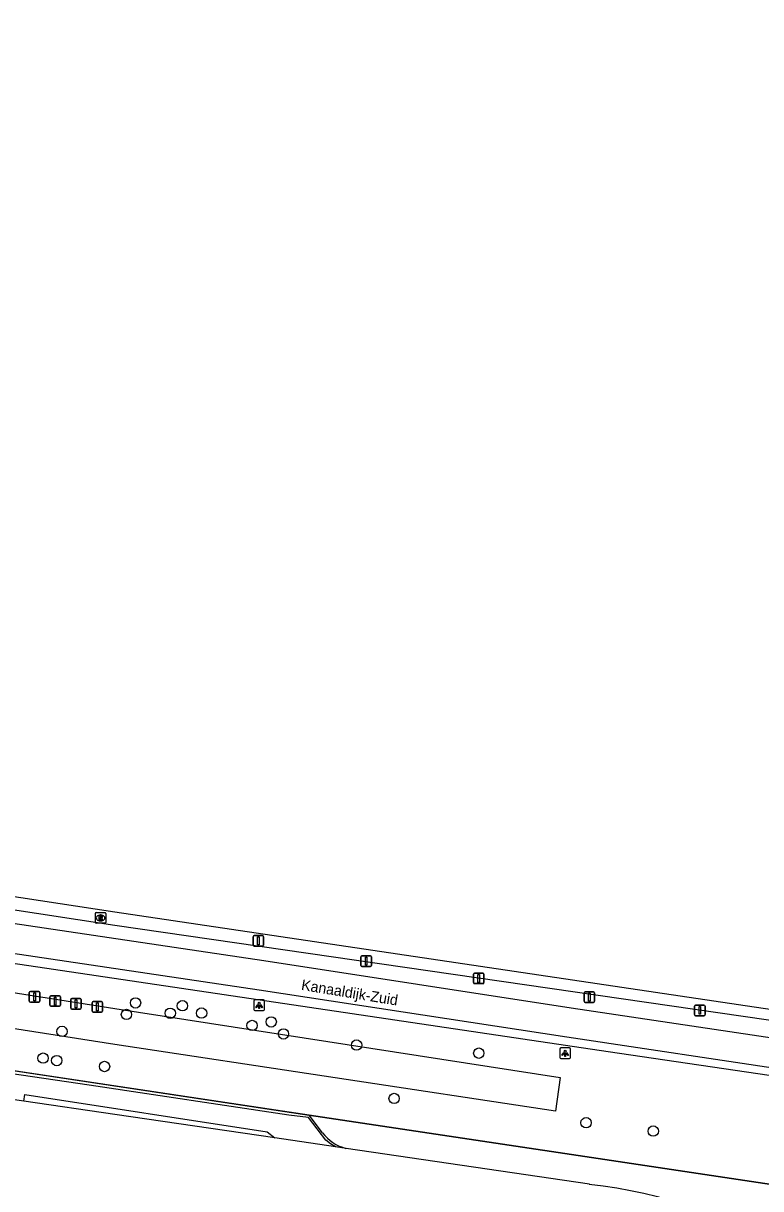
# Model space of a CAD drawing. Extents: x 163046 to 165074, y 382019 to 382874.
# Drawn here: x 164491.3 to 164561, y 382621 to 382731.1 of the extents above; entities that cross this region are included whole.
import ezdxf

# ---------------------------------------------------------------- set-up
doc = ezdxf.new("R2010")
doc.units = 0
for name, color, linetype in [('IMGEO_Afsluitpaal', 7, 'Continuous'), ('IMGEO_Boom', 7, 'Continuous'), ('IMGEO_Fietspad_gesloten', 7, 'Continuous'), ('IMGEO_Groenvoorziening', 7, 'Continuous'), ('IMGEO_Hek', 7, 'Continuous'), ('IMGEO_Lichtpunt', 7, 'Continuous'), ('IMGEO_Openbare_ruimte_label', 7, 'Continuous'), ('IMGEO_Rijbaan_lokaal_gesloten', 7, 'Continuous'), ('IMGEO_Rijbaan_lokaal_halfverhard', 7, 'Continuous'), ('IMGEO_Rioolput', 7, 'Continuous'), ('IMGEO_Waterloop', 7, 'Continuous')]:
    doc.layers.add(name, color=color, linetype=linetype)

msp = doc.modelspace()

# ---------------------------------------------------------------- linework, layer by layer
at = {"layer": 'IMGEO_Afsluitpaal'}
for p, q in [((164513.06, 382643.99), (164513.06, 382644.79)), ((164513.06, 382644.79), (164513.06, 382643.99)), ((164513.16, 382644.89), (164513.95, 382644.89)), ((164513.95, 382644.89), (164513.16, 382644.89)), ((164514.05, 382644.79), (164514.05, 382643.99)), ((164514.05, 382643.99), (164514.05, 382644.79)), ((164513.95, 382643.89), (164513.16, 382643.89)), ((164513.16, 382643.89), (164513.95, 382643.89)), ((164523.25, 382642.07), (164523.25, 382642.87)), ((164523.25, 382642.87), (164523.25, 382642.07)), ((164523.35, 382642.97), (164524.14, 382642.97)), ((164524.14, 382642.97), (164523.35, 382642.97)), ((164524.14, 382641.97), (164523.35, 382641.97)), ((164523.35, 382641.97), (164524.14, 382641.97)), ((164524.24, 382642.87), (164524.24, 382642.07)), ((164524.24, 382642.07), (164524.24, 382642.87)), ((164533.89, 382640.45), (164533.89, 382641.25)), ((164533.89, 382641.25), (164533.89, 382640.45)), ((164533.99, 382641.35), (164534.78, 382641.35)), ((164534.78, 382641.35), (164533.99, 382641.35)), ((164534.88, 382641.25), (164534.88, 382640.45)), ((164534.88, 382640.45), (164534.88, 382641.25)), ((164534.78, 382640.35), (164533.99, 382640.35)), ((164533.99, 382640.35), (164534.78, 382640.35)), ((164491.91, 382638.71), (164491.91, 382639.51)), ((164491.91, 382639.51), (164491.91, 382638.71)), ((164492.01, 382639.61), (164492.8, 382639.61)), ((164492.8, 382639.61), (164492.01, 382639.61)), ((164492.8, 382638.61), (164492.01, 382638.61)), ((164492.01, 382638.61), (164492.8, 382638.61)), ((164492.9, 382639.51), (164492.9, 382638.71)), ((164492.9, 382638.71), (164492.9, 382639.51)), ((164493.86, 382638.31), (164493.86, 382639.11)), ((164493.86, 382639.11), (164493.86, 382638.31)), ((164493.96, 382639.21), (164494.75, 382639.21)), ((164494.75, 382639.21), (164493.96, 382639.21)), ((164494.85, 382639.11), (164494.85, 382638.31)), ((164494.85, 382638.31), (164494.85, 382639.11)), ((164495.82, 382638.05), (164495.82, 382638.85)), ((164495.82, 382638.85), (164495.82, 382638.05)), ((164495.92, 382638.95), (164496.71, 382638.95)), ((164496.71, 382638.95), (164495.92, 382638.95)), ((164496.81, 382638.85), (164496.81, 382638.05)), ((164496.81, 382638.05), (164496.81, 382638.85)), ((164497.95, 382638.65), (164498.74, 382638.65)), ((164498.74, 382638.65), (164497.95, 382638.65)), ((164544.34, 382638.68), (164544.34, 382639.48)), ((164544.34, 382639.48), (164544.34, 382638.68)), ((164544.44, 382639.58), (164545.22, 382639.58)), ((164545.22, 382639.58), (164544.44, 382639.58)), ((164545.32, 382639.48), (164545.32, 382638.68)), ((164545.32, 382638.68), (164545.32, 382639.48)), ((164494.75, 382638.21), (164493.96, 382638.21)), ((164493.96, 382638.21), (164494.75, 382638.21)), ((164496.71, 382637.95), (164495.92, 382637.95)), ((164495.92, 382637.95), (164496.71, 382637.95)), ((164497.85, 382637.75), (164497.85, 382638.55)), ((164497.85, 382638.55), (164497.85, 382637.75)), ((164498.74, 382637.65), (164497.95, 382637.65)), ((164497.95, 382637.65), (164498.74, 382637.65)), ((164498.84, 382638.55), (164498.84, 382637.75)), ((164498.84, 382637.75), (164498.84, 382638.55)), ((164545.22, 382638.58), (164544.44, 382638.58)), ((164544.44, 382638.58), (164545.22, 382638.58)), ((164554.78, 382637.42), (164554.78, 382638.22)), ((164554.78, 382638.22), (164554.78, 382637.42)), ((164554.88, 382638.32), (164555.67, 382638.32)), ((164555.67, 382638.32), (164554.88, 382638.32)), ((164555.77, 382638.22), (164555.77, 382637.42)), ((164555.77, 382637.42), (164555.77, 382638.22)), ((164555.67, 382637.32), (164554.88, 382637.32)), ((164554.88, 382637.32), (164555.67, 382637.32))]:
    msp.add_line(p, q, dxfattribs=at)
for points in [[(164513.48, 382644.77), (164513.63, 382644.77), (164513.63, 382644.02), (164513.48, 382644.02), (164513.48, 382644.77)], [(164523.67, 382642.85), (164523.82, 382642.85), (164523.82, 382642.1), (164523.67, 382642.1), (164523.67, 382642.85)], [(164534.31, 382641.22), (164534.46, 382641.22), (164534.46, 382640.47), (164534.31, 382640.47), (164534.31, 382641.22)], [(164492.33, 382639.49), (164492.48, 382639.49), (164492.48, 382638.74), (164492.33, 382638.74), (164492.33, 382639.49)], [(164494.28, 382639.08), (164494.43, 382639.08), (164494.43, 382638.33), (164494.28, 382638.33), (164494.28, 382639.08)], [(164496.24, 382638.82), (164496.39, 382638.82), (164496.39, 382638.07), (164496.24, 382638.07), (164496.24, 382638.82)], [(164544.75, 382639.45), (164544.9, 382639.45), (164544.9, 382638.7), (164544.75, 382638.7), (164544.75, 382639.45)], [(164498.27, 382638.53), (164498.42, 382638.53), (164498.42, 382637.78), (164498.27, 382637.78), (164498.27, 382638.53)], [(164555.2, 382638.2), (164555.35, 382638.2), (164555.35, 382637.45), (164555.2, 382637.45), (164555.2, 382638.2)]]:
    msp.add_lwpolyline(points, dxfattribs=at)
for centre, start, end in [((164513.16, 382644.79), 90, 180), ((164513.16, 382644.79), 90, 180), ((164513.95, 382644.79), 0, 90), ((164513.95, 382644.79), 360, 90), ((164513.16, 382643.99), 180, 270), ((164513.16, 382643.99), 180, 270), ((164513.95, 382643.99), 270, 0), ((164513.95, 382643.99), 270, 0), ((164523.35, 382642.87), 90, 180), ((164523.35, 382642.87), 90, 180), ((164523.35, 382642.07), 180, 270), ((164523.35, 382642.07), 180, 270), ((164524.14, 382642.87), 0, 90), ((164524.14, 382642.87), 360, 90), ((164524.14, 382642.07), 270, 0), ((164524.14, 382642.07), 270, 0), ((164533.99, 382641.25), 90, 180), ((164533.99, 382641.25), 90, 180), ((164534.78, 382641.25), 0, 90), ((164534.78, 382641.25), 360, 90), ((164533.99, 382640.45), 180, 270), ((164533.99, 382640.45), 180, 270), ((164534.78, 382640.45), 270, 0), ((164534.78, 382640.45), 270, 0), ((164492.01, 382639.51), 90, 180), ((164492.01, 382639.51), 90, 180), ((164492.01, 382638.71), 180, 270), ((164492.01, 382638.71), 180, 270), ((164492.8, 382639.51), 0, 90), ((164492.8, 382639.51), 360, 90), ((164492.8, 382638.71), 270, 0), ((164492.8, 382638.71), 270, 0), ((164493.96, 382639.11), 90, 180), ((164493.96, 382639.11), 90, 180), ((164494.75, 382639.11), 0, 90), ((164494.75, 382639.11), 360, 90), ((164495.92, 382638.85), 90, 180), ((164495.92, 382638.85), 90, 180), ((164496.71, 382638.85), 0, 90), ((164496.71, 382638.85), 360, 90), ((164497.95, 382638.55), 90, 180), ((164497.95, 382638.55), 90, 180), ((164498.74, 382638.55), 0, 90), ((164498.74, 382638.55), 360, 90), ((164544.44, 382639.48), 90, 180), ((164544.44, 382639.48), 90, 180), ((164544.44, 382638.68), 180, 270), ((164544.44, 382638.68), 180, 270), ((164545.22, 382639.48), 0, 90), ((164545.22, 382639.48), 360, 90), ((164545.22, 382638.68), 270, 0), ((164545.22, 382638.68), 270, 0), ((164493.96, 382638.31), 180, 270), ((164493.96, 382638.31), 180, 270), ((164494.75, 382638.31), 270, 0), ((164494.75, 382638.31), 270, 0), ((164495.92, 382638.05), 180, 270), ((164495.92, 382638.05), 180, 270), ((164496.71, 382638.05), 270, 0), ((164496.71, 382638.05), 270, 0), ((164497.95, 382637.75), 180, 270), ((164497.95, 382637.75), 180, 270), ((164498.74, 382637.75), 270, 0), ((164498.74, 382637.75), 270, 0), ((164554.88, 382638.22), 90, 180), ((164554.88, 382638.22), 90, 180), ((164555.67, 382638.22), 0, 90), ((164555.67, 382638.22), 360, 90), ((164554.88, 382637.42), 180, 270), ((164554.88, 382637.42), 180, 270), ((164555.67, 382637.42), 270, 0), ((164555.67, 382637.42), 270, 0)]:
    msp.add_arc(centre, 0.1, start, end, dxfattribs=at)
at = {"layer": 'IMGEO_Boom'}
for centre in [(164501.95, 382638.53), (164506.38, 382638.26), (164501.09, 382637.44), (164505.23, 382637.55), (164508.19, 382637.57), (164512.96, 382636.4), (164514.77, 382636.73), (164495, 382635.84), (164515.93, 382635.6), (164522.84, 382634.55), (164534.39, 382633.78), (164493.21, 382633.31), (164494.5, 382633.08), (164499.02, 382632.52), (164526.39, 382629.5), (164544.53, 382627.21), (164550.88, 382626.42)]:
    msp.add_circle(centre, 0.489, dxfattribs=at)
at = {"layer": 'IMGEO_Fietspad_gesloten'}
for points in [[(163935.71, 382729.35), (163983.8, 382722.23), (164052.71, 382712.03), (164052.69, 382711.93), (164086.54, 382706.99), (164187.43, 382691.72), (164210.53, 382688.01), (164226.5, 382685.65), (164235.35, 382684.54), (164278.14, 382678.22), (164284.35, 382677.28), (164396.3, 382660.19), (164454.95, 382651.33), (164514.06, 382642.55), (164543.13, 382638.08), (164564.45, 382634.88), (164577.4, 382632.94), (164578.83, 382632.68), (164590.1, 382630.98)], [(164520.86, 382624.93), (164520.36, 382625.22), (164519.94, 382625.56), (164518.31, 382627.71), (164516.44, 382627.92), (164497.58, 382630.74), (164458.77, 382636.45), (164437.76, 382639.63), (164406.03, 382644.41), (164348.55, 382652.85), (164290.62, 382661.73), (164274.25, 382664.12)], [(164491.39, 382629.23), (164491.49, 382629.87), (164514.38, 382626.36), (164515.1, 382625.77)]]:
    msp.add_lwpolyline(points, dxfattribs=at)
at = {"layer": 'IMGEO_Groenvoorziening'}
for points in [[(163359.37, 382797.83), (163374.85, 382798.03), (163401.89, 382794.15), (163410.94, 382792.85), (163500, 382779.47), (163535.41, 382774.6), (163550.62, 382772.33), (163693.06, 382751.36), (163828.8, 382731.36), (163846.1, 382728.88), (163873.33, 382724.84), (163916.5, 382718.52), (163943.51, 382714.37), (163981.6, 382708.67), (164080.42, 382694.02), (164103.91, 382690.52), (164197.42, 382676.27), (164217.65, 382673.07), (164282.56, 382663.33), (164518.36, 382627.93)], [(164577.64, 382634.59), (164500, 382645.86), (164326.61, 382672.42), (164284.55, 382678.7)], [(164518.36, 382627.93), (164562.67, 382621.28)], [(164519.63, 382626.25), (164518.36, 382627.93)]]:
    msp.add_lwpolyline(points, dxfattribs=at)
msp.add_arc((164522.82, 382628.66), 4, 217.0042, 255.7236, dxfattribs=at)
at = {"layer": 'IMGEO_Hek'}
for points in [[(164518.36, 382627.93), (164282.56, 382663.33)], [(164562.67, 382621.28), (164518.36, 382627.93)]]:
    msp.add_lwpolyline(points, dxfattribs=at)
at = {"layer": 'IMGEO_Lichtpunt'}
for p, q in [((164513.14, 382638.71), (164513.14, 382637.9)), ((164513.14, 382638.71), (164513.14, 382637.9)), ((164514.04, 382638.81), (164513.23, 382638.81)), ((164514.04, 382638.81), (164513.23, 382638.81)), ((164514.13, 382637.9), (164514.13, 382638.71)), ((164514.13, 382637.9), (164514.13, 382638.71)), ((164513.23, 382637.81), (164514.04, 382637.81)), ((164513.23, 382637.81), (164514.04, 382637.81)), ((164542.95, 382634.27), (164542.14, 382634.27)), ((164542.95, 382634.27), (164542.14, 382634.27)), ((164542.05, 382634.17), (164542.05, 382633.37)), ((164542.05, 382634.17), (164542.05, 382633.37)), ((164542.14, 382633.27), (164542.95, 382633.27)), ((164542.14, 382633.27), (164542.95, 382633.27)), ((164543.05, 382633.37), (164543.05, 382634.17)), ((164543.05, 382633.37), (164543.05, 382634.17))]:
    msp.add_line(p, q, dxfattribs=at)
for points in [[(164513.51, 382638.37), (164513.55, 382638.35), (164513.36, 382638.08), (164513.32, 382638.11), (164513.51, 382638.37)], [(164513.61, 382638.33), (164513.66, 382638.33), (164513.66, 382638), (164513.61, 382638), (164513.61, 382638.33)], [(164513.72, 382638.35), (164513.76, 382638.37), (164513.95, 382638.11), (164513.91, 382638.08), (164513.72, 382638.35)], [(164542.42, 382633.84), (164542.46, 382633.81), (164542.27, 382633.55), (164542.24, 382633.58), (164542.42, 382633.84)], [(164542.52, 382633.79), (164542.57, 382633.79), (164542.57, 382633.47), (164542.52, 382633.47), (164542.52, 382633.79)], [(164542.63, 382633.81), (164542.67, 382633.84), (164542.86, 382633.57), (164542.82, 382633.55), (164542.63, 382633.81)]]:
    msp.add_lwpolyline(points, dxfattribs=at)
for centre in [(164513.64, 382638.51), (164542.55, 382633.97)]:
    msp.add_circle(centre, 0.0994, dxfattribs=at)
for centre, start, end in [((164513.23, 382638.71), 90, 180), ((164513.23, 382638.71), 90, 180), ((164514.04, 382638.71), 0, 90), ((164514.04, 382638.71), 0, 90), ((164513.23, 382637.9), 180, 270), ((164513.23, 382637.9), 180, 270), ((164514.04, 382637.9), 270, 0), ((164514.04, 382637.9), 270, 360), ((164542.14, 382634.17), 90, 180), ((164542.14, 382634.17), 90, 180), ((164542.95, 382634.17), 0, 90), ((164542.95, 382634.17), 0, 90), ((164542.14, 382633.37), 180, 270), ((164542.14, 382633.37), 180, 270), ((164542.95, 382633.37), 270, 0), ((164542.95, 382633.37), 270, 360)]:
    msp.add_arc(centre, 0.0946, start, end, dxfattribs=at)
at = {"layer": 'IMGEO_Rijbaan_lokaal_gesloten'}
for points in [[(164491.39, 382629.23), (164484.23, 382630.28), (164472.49, 382631.88)], [(164515.1, 382625.77), (164500, 382627.97), (164491.39, 382629.23)], [(164520.86, 382624.93), (164515.1, 382625.77)], [(164521.84, 382624.78), (164520.86, 382624.93)], [(164544.84, 382621.39), (164521.84, 382624.78)]]:
    msp.add_lwpolyline(points, dxfattribs=at)
msp.add_arc((164539.62, 382574.77), 46.9, 32.912, 83.6189, dxfattribs=at)
at = {"layer": 'IMGEO_Rijbaan_lokaal_halfverhard'}
for points in [[(163935.2, 382726.45), (163983.27, 382719.37), (164086.12, 382704.22), (164199.47, 382687.05), (164210.1, 382685.24), (164226.11, 382682.88), (164234.94, 382681.77), (164277.72, 382675.46), (164283.96, 382674.5), (164395.88, 382657.42), (164454.54, 382648.56), (164513.64, 382639.78), (164542.71, 382635.32), (164564.09, 382632.1), (164578.55, 382629.91), (164583.76, 382629.04)], [(164563.98, 382631.34), (164546.63, 382633.89), (164490.17, 382642.3), (164454.45, 382647.37), (164396.2, 382656.23), (164325.74, 382667.17), (164243.96, 382679.59)]]:
    msp.add_lwpolyline(points, dxfattribs=at)
at = {"layer": 'IMGEO_Rioolput'}
for p, q in [((164498.15, 382646.14), (164498.15, 382646.99)), ((164498.22, 382647.06), (164499.07, 382647.06)), ((164498.63, 382646.84), (164498.66, 382646.84)), ((164499.15, 382646.99), (164499.15, 382646.14)), ((164499.07, 382646.06), (164498.22, 382646.06)), ((164498.66, 382646.28), (164498.63, 382646.28))]:
    msp.add_line(p, q, dxfattribs=at)
for points in [[(164498.15, 382646.14), (164498.15, 382646.99)], [(164498.22, 382647.06), (164499.07, 382647.06)], [(164498.73, 382646.76), (164498.48, 382646.76), (164498.48, 382646.36)], [(164498.48, 382646.36), (164498.61, 382646.36), (164498.61, 382646.53), (164498.62, 382646.53)], [(164498.66, 382646.68), (164498.61, 382646.68), (164498.61, 382646.6)], [(164498.61, 382646.6), (164498.66, 382646.6)], [(164498.66, 382646.5), (164498.74, 382646.36), (164498.87, 382646.36), (164498.81, 382646.49)], [(164499.15, 382646.99), (164499.15, 382646.14)], [(164499.07, 382646.06), (164498.22, 382646.06)]]:
    msp.add_lwpolyline(points, dxfattribs=at)
for centre, radius, start, end in [((164498.22, 382646.99), 0.0765, 91.552, 178.448), ((164498.22, 382646.99), 0.0765, 91.552, 178.448), ((164498.62, 382646.47), 0.0533, 26.0293, 88.6989), ((164498.67, 382646.59), 0.0964, 77.0061, 93.1865), ((164498.64, 382646.79), 0.19, 274.7715, 282.9687), ((164498.68, 382646.64), 0.0378, 276.6634, 79.6772), ((164498.73, 382646.65), 0.109, 350.3612, 89.416), ((164498.73, 382646.65), 0.112, 277.5842, 350.9817), ((164498.72, 382646.44), 0.108, 29.5134, 73.7905), ((164499.07, 382646.99), 0.0765, 1.552, 88.448), ((164499.07, 382646.99), 0.0765, 1.552, 88.448), ((164498.22, 382646.14), 0.0765, 181.552, 268.448), ((164498.22, 382646.14), 0.0765, 181.552, 268.448), ((164499.07, 382646.14), 0.0765, 271.552, 358.448), ((164499.07, 382646.14), 0.0765, 271.552, 358.448)]:
    msp.add_arc(centre, radius, start, end, dxfattribs=at)
for centre, major_axis, ratio, start_param, end_param in [((164498.63, 382646.56), (-0.387, 0.002), 0.722429, 4.712389, 7.853982), ((164498.66, 382646.56), (-0.39, 0.002), 0.717154, 1.570796, 4.712389)]:
    msp.add_ellipse(centre, major_axis=major_axis, ratio=ratio, start_param=start_param, end_param=end_param, dxfattribs=at)
at = {"layer": 'IMGEO_Waterloop'}
for points in [[(164284.68, 382679.59), (164301.17, 382677.11), (164390.46, 382663.82), (164500, 382647.13), (164577.79, 382635.57)], [(164229.4, 382676.95), (164337.68, 382660.69), (164416.83, 382649.81), (164431.81, 382647.48), (164450.46, 382644.94), (164486.15, 382640.16), (164500, 382638.01), (164542.07, 382631.47), (164541.63, 382628.3), (164500, 382634.6), (164485.67, 382636.85), (164404.8, 382648.54), (164314.83, 382661.08), (164228.97, 382674.04), (164229.4, 382676.95)]]:
    msp.add_lwpolyline(points, dxfattribs=at)

# ---------------------------------------------------------------- texts
at = {"layer": 'IMGEO_Openbare_ruimte_label'}
msp.add_text('Kanaaldijk-Zuid', height=1, rotation=350.6789, dxfattribs=at).set_placement((164517.56, 382639.77))

doc.saveas('drawing.dxf')
